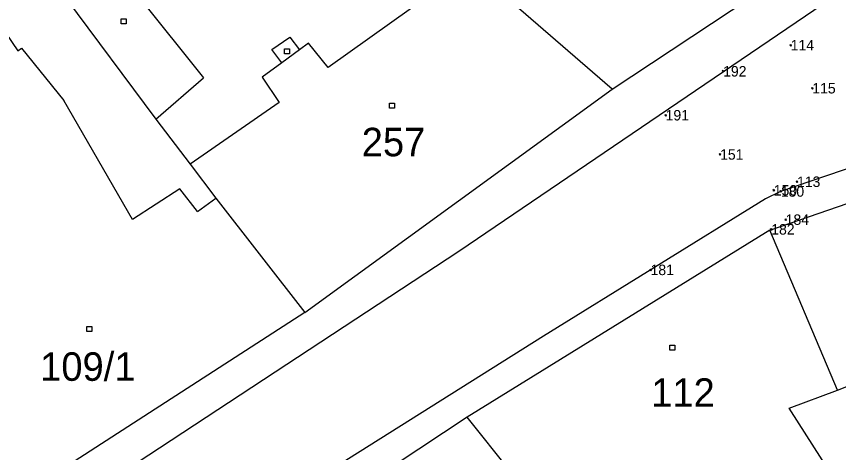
# Model space of a CAD drawing. Extents: x -711879 to -711361, y -1048782 to -1048177.
# Drawn here: x -711718.91 to -711669.86, y -1048568.75 to -1048542.72 of the extents above; entities that cross this region are included whole.
import ezdxf

# ---------------------------------------------------------------- set-up
doc = ezdxf.new("R2010")
doc.units = 0
for name, color, linetype in [('body', 7, 'Continuous'), ('Vrstva 1', 7, 'Continuous'), ('Vrstva 15', 7, 'Continuous'), ('Vrstva 2', 7, 'Continuous'), ('Vrstva 20', 7, 'Continuous'), ('Vrstva 25', 7, 'Continuous'), ('Vrstva 41', 7, 'Continuous'), ('Vrstva 46', 7, 'Continuous')]:
    doc.layers.add(name, color=color, linetype=linetype)

msp = doc.modelspace()

# ---------------------------------------------------------------- linework, layer by layer
at = {"layer": 'Vrstva 1'}
for p, q in [((-711683.36, -1048547.06), (-711665.54, -1048535.25)), ((-711717.84, -1048539.08), (-711710.59, -1048548.86)), ((-711683.36, -1048547.06), (-711691.92, -1048539.67)), ((-711701.7, -1048560.4), (-711683.36, -1048547.06)), ((-711710.59, -1048548.86), (-711708.54, -1048551.55)), ((-711708.54, -1048551.55), (-711707.01, -1048553.57)), ((-711673.96, -1048555.47), (-711666.1, -1048552.77)), ((-711707.01, -1048553.57), (-711701.7, -1048560.4)), ((-711673.96, -1048555.47), (-711692.02, -1048566.63)), ((-711669.92, -1048565.02), (-711673.96, -1048555.47)), ((-711701.7, -1048560.4), (-711721.23, -1048572.99)), ((-711672.81, -1048566.11), (-711669.92, -1048565.02)), ((-711669.91, -1048570.62), (-711672.81, -1048566.11)), ((-711692.02, -1048566.63), (-711696.32, -1048569.48)), ((-711685.22, -1048575.16), (-711692.02, -1048566.63))]:
    msp.add_line(p, q, dxfattribs=at)
at = {"layer": 'Vrstva 2'}
for p, q in [((-711692.52, -1048556.74), (-711664.62, -1048537.77)), ((-711713.84, -1048538.78), (-711707.75, -1048546.38)), ((-711695.34, -1048542.23), (-711700.32, -1048545.78)), ((-711719.94, -1048543.16), (-711718.83, -1048544.77)), ((-711703.67, -1048544.7), (-711702.59, -1048543.97)), ((-711702.59, -1048543.97), (-711702.02, -1048544.71)), ((-711701.48, -1048544.32), (-711702.02, -1048544.71)), ((-711700.32, -1048545.78), (-711701.48, -1048544.32)), ((-711718.83, -1048544.77), (-711718.61, -1048544.62)), ((-711718.61, -1048544.62), (-711716.09, -1048547.75)), ((-711703.08, -1048545.49), (-711703.67, -1048544.7)), ((-711702.02, -1048544.71), (-711703.08, -1048545.49)), ((-711703.08, -1048545.49), (-711704.25, -1048546.35)), ((-711710.59, -1048548.86), (-711707.75, -1048546.38)), ((-711704.25, -1048546.35), (-711703.23, -1048547.87)), ((-711711.98, -1048554.84), (-711716.09, -1048547.75)), ((-711703.23, -1048547.87), (-711708.54, -1048551.55)), ((-711660.61, -1048548.8), (-711673.32, -1048553.18)), ((-711709.16, -1048553.02), (-711711.98, -1048554.84)), ((-711708.11, -1048554.36), (-711709.16, -1048553.02)), ((-711673.32, -1048553.18), (-711674.22, -1048553.61)), ((-711708.11, -1048554.36), (-711707.01, -1048553.57)), ((-711674.22, -1048553.61), (-711687.47, -1048561.81)), ((-711712.4, -1048569.8), (-711692.52, -1048556.74)), ((-711687.47, -1048561.81), (-711745.53, -1048598.31)), ((-711669.92, -1048565.02), (-711667.84, -1048564.2))]:
    msp.add_line(p, q, dxfattribs=at)
at = {"layer": 'Vrstva 20'}
for p, q in [((-711672.72, -1048544.44), (-711672.77, -1048544.39)), ((-711672.72, -1048544.44), (-711672.77, -1048544.49)), ((-711672.72, -1048544.44), (-711672.67, -1048544.39)), ((-711672.72, -1048544.44), (-711672.67, -1048544.49)), ((-711676.75, -1048546), (-711676.8, -1048545.95)), ((-711676.75, -1048546), (-711676.7, -1048545.95)), ((-711676.75, -1048546), (-711676.8, -1048546.05)), ((-711676.75, -1048546), (-711676.7, -1048546.05)), ((-711671.43, -1048547.01), (-711671.48, -1048546.96)), ((-711671.43, -1048547.01), (-711671.38, -1048546.96)), ((-711671.43, -1048547.01), (-711671.48, -1048547.06)), ((-711671.43, -1048547.01), (-711671.38, -1048547.06)), ((-711680.18, -1048548.62), (-711680.23, -1048548.57)), ((-711680.18, -1048548.62), (-711680.23, -1048548.67)), ((-711680.18, -1048548.62), (-711680.13, -1048548.57)), ((-711680.18, -1048548.62), (-711680.13, -1048548.67)), ((-711676.93, -1048550.96), (-711676.98, -1048550.91)), ((-711676.93, -1048550.96), (-711676.98, -1048551.01)), ((-711676.93, -1048550.96), (-711676.88, -1048550.91)), ((-711676.93, -1048550.96), (-711676.88, -1048551.01)), ((-711672.34, -1048552.59), (-711672.39, -1048552.54)), ((-711672.34, -1048552.59), (-711672.39, -1048552.64)), ((-711672.34, -1048552.59), (-711672.29, -1048552.54)), ((-711672.34, -1048552.59), (-711672.29, -1048552.64)), ((-711673.73, -1048553.1), (-711673.78, -1048553.05)), ((-711673.73, -1048553.1), (-711673.78, -1048553.15)), ((-711673.73, -1048553.1), (-711673.68, -1048553.05)), ((-711673.73, -1048553.1), (-711673.68, -1048553.15)), ((-711673.31, -1048553.17), (-711673.36, -1048553.12)), ((-711673.31, -1048553.17), (-711673.36, -1048553.22)), ((-711673.31, -1048553.17), (-711673.26, -1048553.12)), ((-711673.31, -1048553.17), (-711673.26, -1048553.22)), ((-711673.02, -1048554.85), (-711673.07, -1048554.8)), ((-711673.02, -1048554.85), (-711672.97, -1048554.8)), ((-711673.02, -1048554.85), (-711673.07, -1048554.9)), ((-711673.02, -1048554.85), (-711672.97, -1048554.9)), ((-711673.88, -1048555.43), (-711673.93, -1048555.38)), ((-711673.88, -1048555.43), (-711673.93, -1048555.48)), ((-711673.88, -1048555.43), (-711673.83, -1048555.38)), ((-711673.88, -1048555.43), (-711673.83, -1048555.48)), ((-711681.08, -1048557.85), (-711681.13, -1048557.8)), ((-711681.08, -1048557.85), (-711681.13, -1048557.9)), ((-711681.08, -1048557.85), (-711681.03, -1048557.8)), ((-711681.08, -1048557.85), (-711681.03, -1048557.9))]:
    msp.add_line(p, q, dxfattribs=at)
at = {"layer": 'Vrstva 25'}
for p, q in [((-711712.67, -1048542.86), (-711712.37, -1048542.86)), ((-711712.67, -1048543.16), (-711712.67, -1048542.86)), ((-711712.37, -1048542.86), (-711712.37, -1048543.16)), ((-711712.37, -1048543.16), (-711712.67, -1048543.16)), ((-711702.92, -1048544.66), (-711702.62, -1048544.66)), ((-711702.92, -1048544.96), (-711702.92, -1048544.66)), ((-711702.62, -1048544.96), (-711702.92, -1048544.96)), ((-711702.62, -1048544.66), (-711702.62, -1048544.96)), ((-711696.65, -1048547.9), (-711696.35, -1048547.9)), ((-711696.65, -1048548.2), (-711696.65, -1048547.9)), ((-711696.35, -1048547.9), (-711696.35, -1048548.2)), ((-711696.35, -1048548.2), (-711696.65, -1048548.2)), ((-711714.71, -1048561.22), (-711714.41, -1048561.22)), ((-711714.71, -1048561.52), (-711714.71, -1048561.22)), ((-711714.41, -1048561.52), (-711714.71, -1048561.52)), ((-711714.41, -1048561.22), (-711714.41, -1048561.52)), ((-711679.93, -1048562.34), (-711679.63, -1048562.34)), ((-711679.93, -1048562.64), (-711679.93, -1048562.34)), ((-711679.63, -1048562.64), (-711679.93, -1048562.64)), ((-711679.63, -1048562.34), (-711679.63, -1048562.64))]:
    msp.add_line(p, q, dxfattribs=at)
at = {"layer": 'Vrstva 41'}
for p, q in [((-711672.72, -1048544.44), (-711672.72, -1048544.44)), ((-711676.75, -1048546), (-711676.75, -1048546)), ((-711671.43, -1048547.01), (-711671.43, -1048547.01)), ((-711680.18, -1048548.62), (-711680.18, -1048548.62)), ((-711676.93, -1048550.96), (-711676.93, -1048550.96)), ((-711672.34, -1048552.59), (-711672.34, -1048552.59)), ((-711673.73, -1048553.1), (-711673.73, -1048553.1)), ((-711673.31, -1048553.17), (-711673.31, -1048553.17)), ((-711673.02, -1048554.85), (-711673.02, -1048554.85)), ((-711673.88, -1048555.43), (-711673.88, -1048555.43)), ((-711681.08, -1048557.85), (-711681.08, -1048557.85))]:
    msp.add_line(p, q, dxfattribs=at)
at = {"layer": 'Vrstva 46'}
for p, q in [((-711718.83, -1048544.77), (-711718.83, -1048544.77)), ((-711718.61, -1048544.62), (-711718.61, -1048544.62)), ((-711716.09, -1048547.75), (-711716.09, -1048547.75)), ((-711709.16, -1048553.02), (-711709.16, -1048553.02)), ((-711708.11, -1048554.36), (-711708.11, -1048554.36)), ((-711711.98, -1048554.84), (-711711.98, -1048554.84)), ((-711673.96, -1048555.47), (-711673.96, -1048555.47)), ((-711692.02, -1048566.63), (-711692.02, -1048566.63))]:
    msp.add_line(p, q, dxfattribs=at)

# ---------------------------------------------------------------- texts
at = {"layer": 'body'}
for s, p in [('114', (-711672.72, -1048544.753)), ('192', (-711676.75, -1048546.312)), ('115', (-711671.43, -1048547.323)), ('191', (-711680.18, -1048548.932)), ('151', (-711676.93, -1048551.273)), ('113', (-711672.34, -1048552.902)), ('150', (-711673.73, -1048553.412)), ('180', (-711673.31, -1048553.483)), ('184', (-711673.02, -1048555.162)), ('182', (-711673.88, -1048555.743)), ('181', (-711681.08, -1048558.162))]:
    msp.add_text(s, height=0.625, dxfattribs=at).set_placement(p)
at = {"layer": 'Vrstva 15'}
for s, p in [('257', (-711698.31, -1048551.07)), ('109/1', (-711717.496, -1048564.47)), ('112', (-711681.04, -1048566.02))]:
    msp.add_text(s, height=1.7, dxfattribs=at).set_placement(p)

doc.saveas('drawing.dxf')
